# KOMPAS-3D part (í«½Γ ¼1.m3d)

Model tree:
1. Эскиз:1
2. Операция выдавливания:1
     Расстояние 1 = 4; Расстояние 2 = 8
3. Эскиз:2
4. Операция выдавливания:2
     Расстояние 1 = 0.5; Расстояние 2 = 8
5. Скругление:1
     Радиус = 0.2

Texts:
  болт м1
